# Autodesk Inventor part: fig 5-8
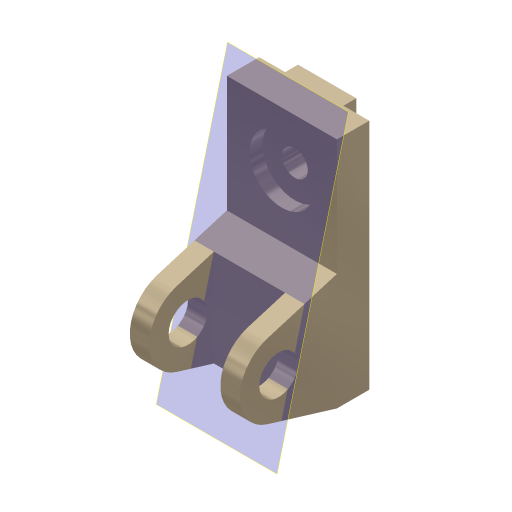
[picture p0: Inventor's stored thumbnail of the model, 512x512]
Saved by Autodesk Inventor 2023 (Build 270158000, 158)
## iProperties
Created: 2001-11
Part Number: fig 5-8
Document SubType Name: Modeling
Designer: Renu Muthoo
Density: 1 g/cm^3
Material: Generic
Appearance: Metal-Titanium (Polished)
Control State: 0
Master: False
Checked Out: False
Shininess: 65.0
Angle Display Precision: 2
Document Length Units: 11269
Document Angle Units: 11279
Document Time Units: 11290
Document Mass Units: 11283
Document Length Units Precision: 3
Document Angle Units Precision: 2
Compacted: False
Density: 0.0
Volumn: 0.0
Area: 0.0
PropertySet Name: Model Information
Author: Renu Muthoo
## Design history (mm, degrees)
node "Sketch1"
sketch "Sketch2"
  geometry: L1 (33.257, 104.664)-(33.257, -75.336); L2 (33.257, -75.336)-(8.257, -75.336); L3 (8.257, -75.336)-(-45.451, -59.045); L4 (-45.451, -1.628)-(8.257, 14.664); L5 (8.257, 14.664)-(8.257, 104.664); L6 (8.257, 104.664)-(33.257, 104.664); C1 r 15 at (-36.743, -30.336); A1 r 30 centre (-36.743, -30.336) between (-45.451, -1.628) and (-45.451, -59.045)
  constraints: 12 end point, 2 centre point, 2 equal length, 2 parallel, 2 point on circle, 2 tangent, 1 coincident, 1 perpendicular, 1 vertical
  dimensions: "d0" = 180 distance of L1.start L1.end; "d1" = 30 radius of A1; "d2" = 25 distance of L5.end L1.start; "d3" = 45 distance from line of L2 A1.centre; "d4" = 70 distance from line of L1 A1.centre; "d5" = 30 diameter of C1
extrude "Extrusion1" new body sketch "Sketch2" distance "d6" = 85; taper "d7" = 0 deg
workplane "Work Plane1"
sketch "Sketch3"
  geometry: L1 (15, 62.364)-(70, 62.364); L2 (70, 62.364)-(70, -52.386); L3 (70, -52.386)-(15, -52.386); L4 (15, -52.386)-(15, 62.364); L5 (0, -45)-(0, -28.708) reference
  constraints: 8 end point, 2 parallel, 1 horizontal, 1 perpendicular
  dimensions: "d8" = 55 distance of L1.start L1.end; "d9" = 15 distance between parallel lines of L5 L4
extrude "Extrusion2" cut sketch "Sketch3" distance "d10" = 50; taper "d11" = 0 deg
sketch "Sketch4"
  geometry: L1 (0, 25)-(85, 25) reference; L2 (0, 0)-(0, 25) reference; L3 (20, 25)-(65, 25); L4 (65, 25)-(65, 35); L5 (65, 35)-(20, 35); L6 (20, 35)-(20, 25)
  constraints: 8 end point, 2 parallel, 1 horizontal, 1 perpendicular, 1 point on line
  dimensions: "d12" = 45 distance of L4.end L5.end; "d13" = 10 distance of L3.end L4.end; "d14" = 20 distance between parallel lines of L2 L6
extrude "Extrusion3" join sketch "Sketch4" stored distance "d15" = 50; taper "d16" = 0 deg
sketch "Sketch5"
  geometry: L1 (85, 0)-(85, 90) reference; L2 (0, 90)-(85, 90) reference; 1 further point
  dimensions: "d17" = 42 distance from line of L2 point (42.5, 48); "d18" = 42.5 distance from line of L1 point (42.5, 48)
hole "Hole1" sketch "Sketch5" at (42.5, 48) diameter "d19" = 20; stored, may be unused: countersink angle "d23" = 82 deg, drill point angle "d25" = 118 deg; dims "d20" = 6, "d21" = 50, "d22" = 10, "d24" = 8
workplane "Work Plane5"
body "Solid1"
